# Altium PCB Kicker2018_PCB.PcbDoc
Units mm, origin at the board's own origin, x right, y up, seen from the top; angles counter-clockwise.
Board outline 66.22 x 43.08 mm, 2 copper layers (Top Layer, Bottom Layer); 38 components, 26 nets, 134 pads, 5 vias.
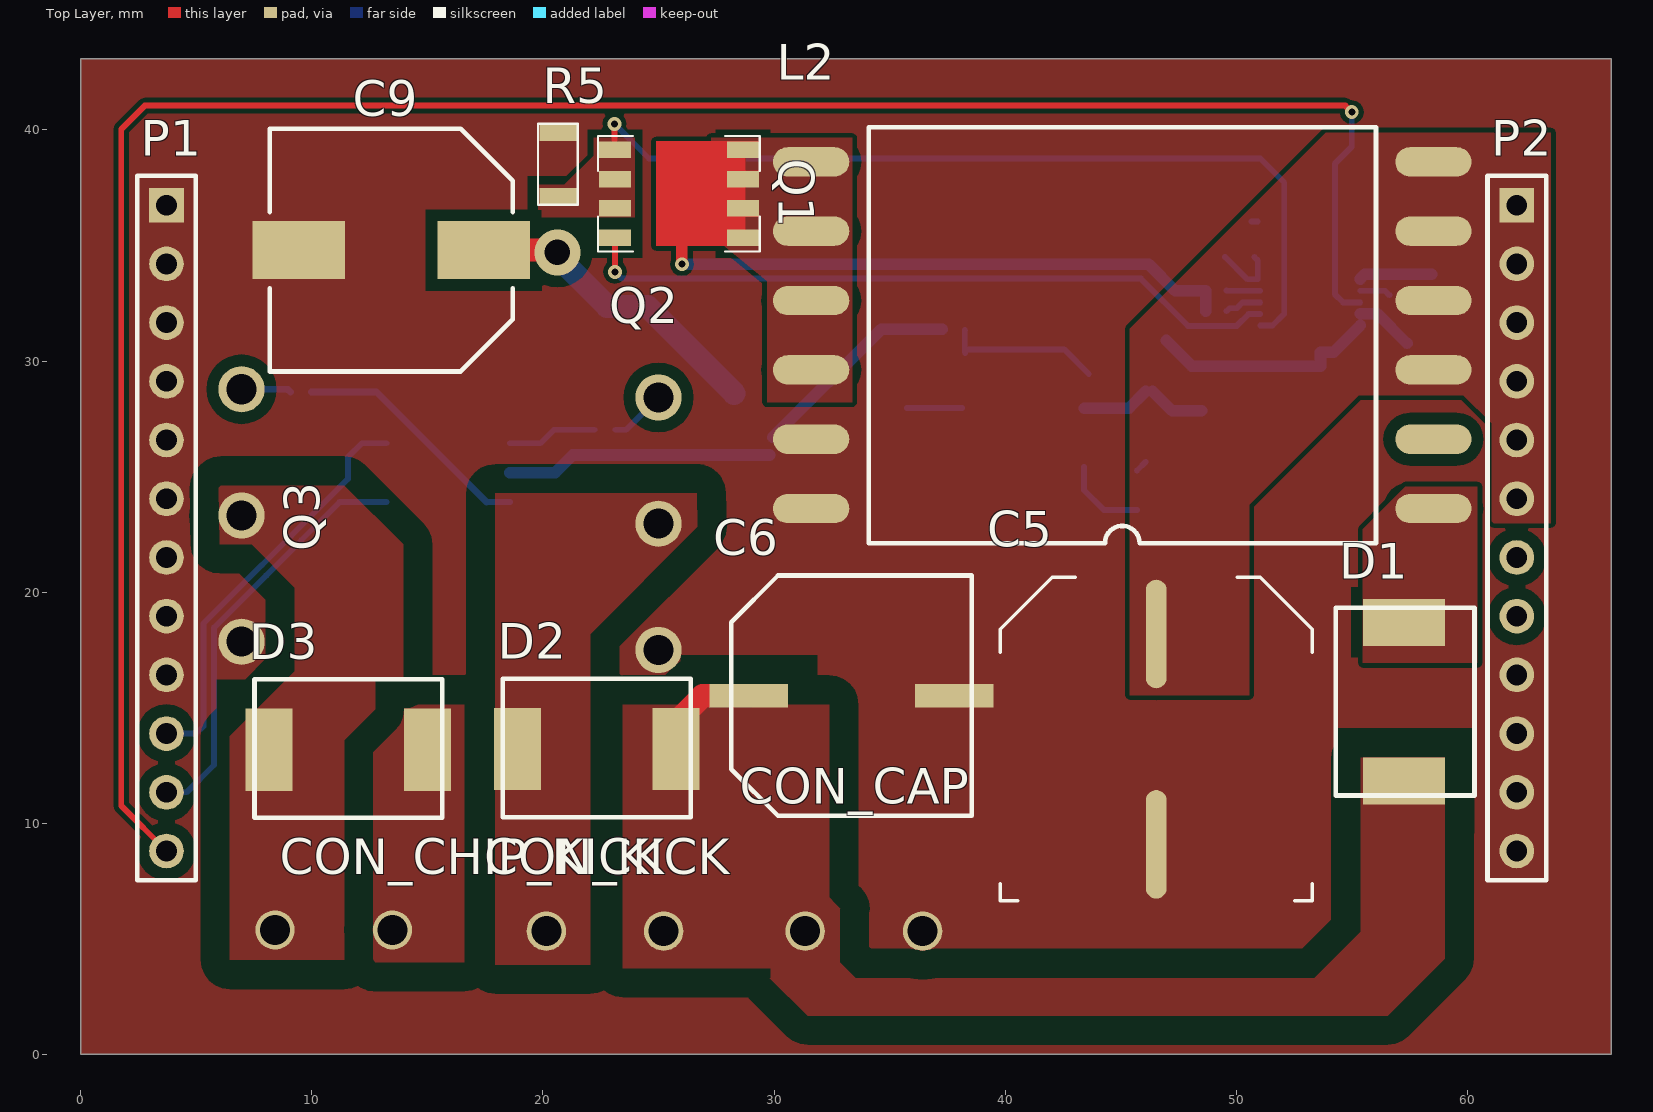
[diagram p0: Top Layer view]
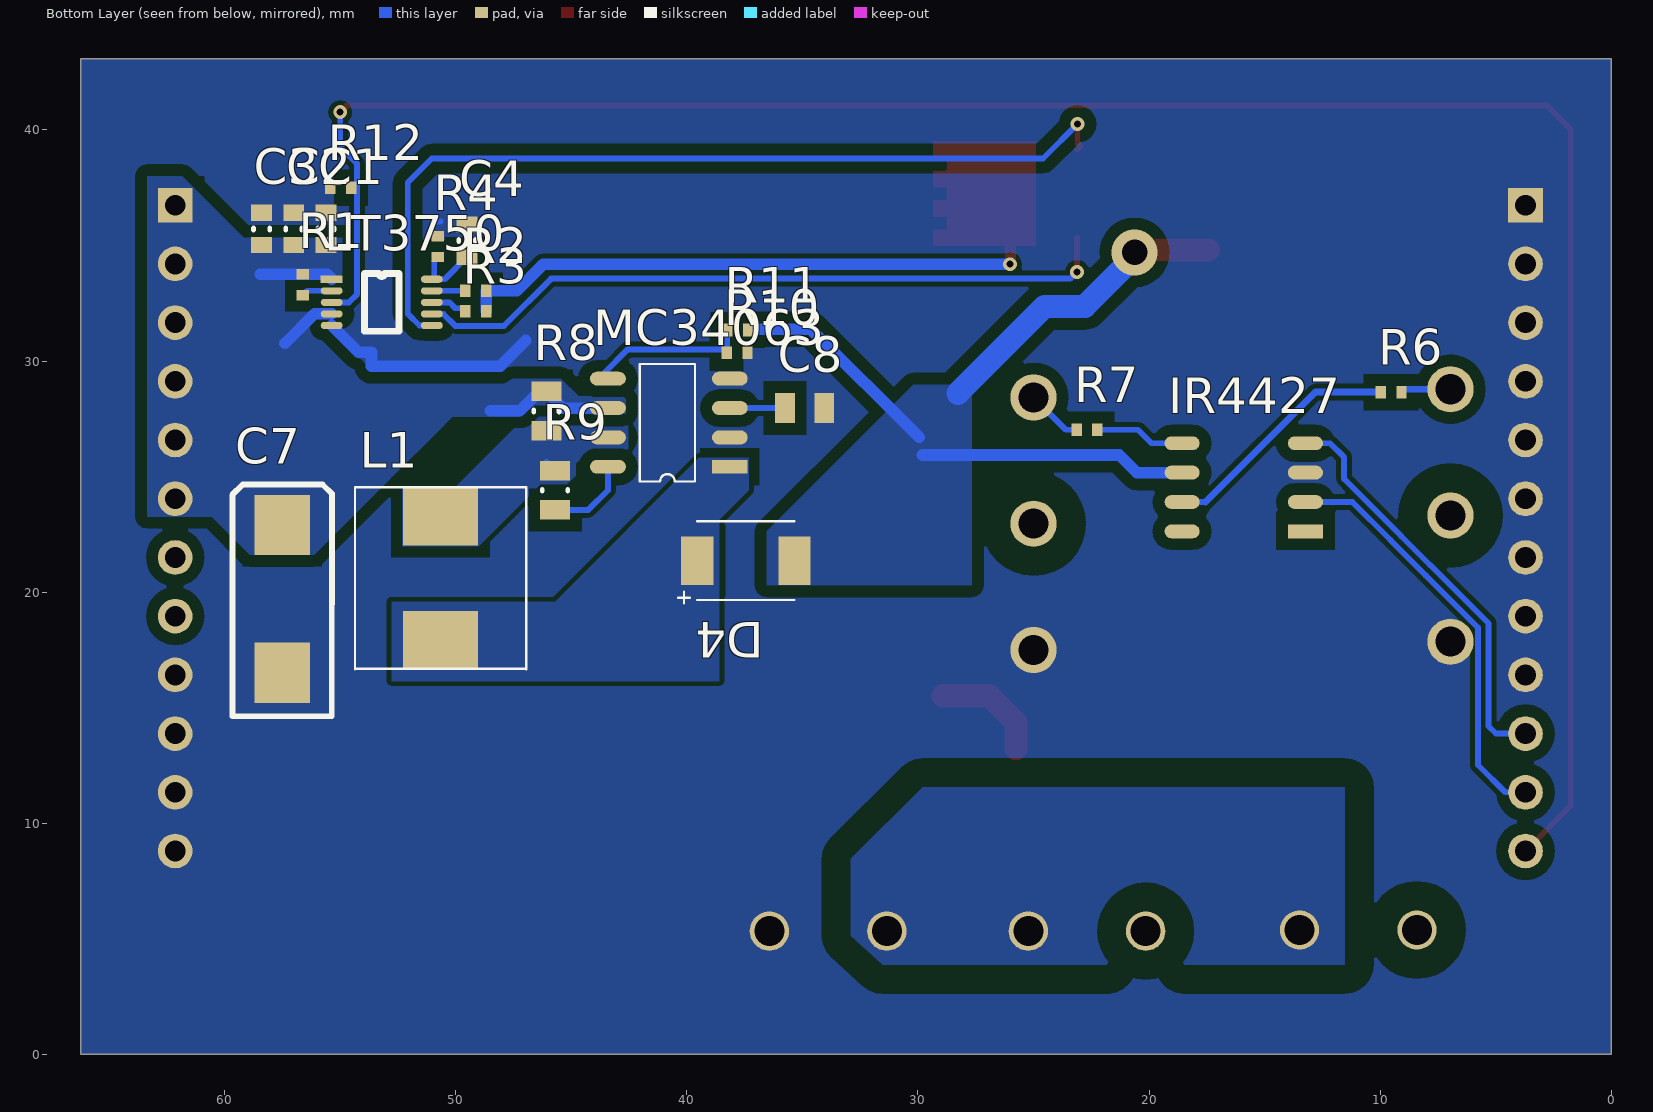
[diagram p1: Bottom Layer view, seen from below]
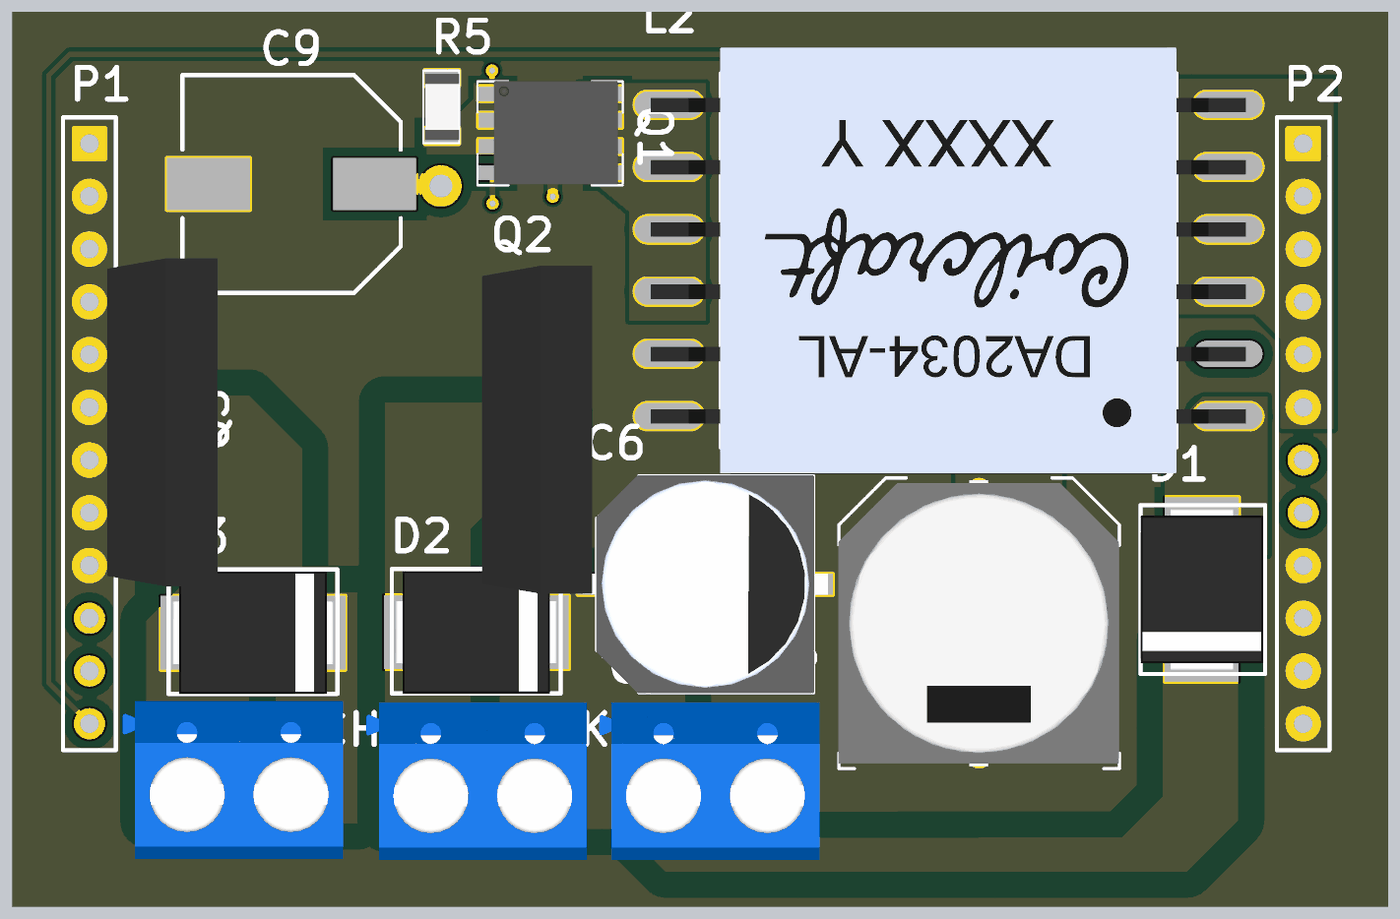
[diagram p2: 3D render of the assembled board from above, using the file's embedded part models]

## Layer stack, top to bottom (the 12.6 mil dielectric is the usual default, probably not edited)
Top Solder: solder mask 0.0102, Solder Resist, Dk 3.5
Top Layer: signal copper 0.0356
Dielectric 1: dielectric 0.32, FR-4, Dk 4.8
Bottom Layer: signal copper 0.0356
Bottom Solder: solder mask 0.0102, Solder Resist, Dk 3.5

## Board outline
0,43.078 0,0 66.218,0 66.218,43.078

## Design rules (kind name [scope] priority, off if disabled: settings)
Clearance "Vs Clearence" [InNet('Vs')] p1: gap=0.5 ignorepadtopadclearanceinfootprint=TRUE
Clearance NetLT3750_6 [OnLayer('Bottom Layer') vs InNet('NetLT3750_6')] p2: gap=0.5 ignorepadtopadclearanceinfootprint=TRUE
Clearance "VCC Clearence" [InNet('VCC') vs OnLayer('Bottom Layer')] p3: gap=0.5 ignorepadtopadclearanceinfootprint=TRUE
Clearance HV [InNetClass('HV')] p4: gap=1.25 ignorepadtopadclearanceinfootprint=TRUE
Clearance [All] p5: gap=0.2 ignorepadtopadclearanceinfootprint=TRUE except(0.5: SMDPad-Poly THPad-Poly)
Height [All] p1: minheight=0 maxheight=50 prefheight=12.7
PlaneConnect [All] p1: planeconnectstyle=Direct reliefexpansion=0.508 reliefentries=4 reliefconductorwidth=0.254 reliefairgap=0.254
PolygonConnect [All] p1: connectstyle=Direct reliefconductorwidth=0.254 reliefentries=4 polygonreliefangle="90 Angle" airgapwidth=0.254
RoutingVias [All] p1: holewidth=0.711 width=1.27 viastyle="Through Hole" minholewidth=0.711 minwidth=1.27 maxholewidth=0.711 maxwidth=1.27
SolderMaskExpansion [All] p1: expansion=0.102
Width [All] p1: maxlimit=5 minlimit=0.254 preferedwidth=0.254
28 further rules are at their usual default settings.

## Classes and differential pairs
net class HV: Cap+ CHIP_KICK- KICK-

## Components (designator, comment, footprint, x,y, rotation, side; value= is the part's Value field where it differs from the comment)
C1 "10uF" CAPC0603(1608)55_L 55.601,35.712 r90 bottom
C2 "10uF" CAPC0603(1608)55_L 56.998,35.712 r90 bottom
C3 "10uF" CAPC0603(1608)55_L 58.395,35.712 r90 bottom
C4 "100pF" CAPC0603(1608)55_L 49.505,35.204 r270 bottom
C5 "100uF" PCBComponent#1 46.533,13.64 r180 top
C6 "22uF" "CAP ALUM 22UF 250V" 33.35,15.519 r180 top
C7 "100uF" 7343-CAPPOL 57.506,19.71 r270 bottom
C8 "180pF" 0805-CAP 34.9,27.965 r0 bottom
C9 "220uF" NIC-CAPA2-10X10_V 13.437,34.798 r180 top
CON_CAP "OSTTA024163" "Term Block 2P" 33.884,5.334 r0 top
CON_CHIP_KICK "OSTTA024163" "Term Block 2P" 10.947,5.385 r0 top
CON_KICK "OSTTA024163" "Term Block 2P" 22.682,5.334 r0 top
D1 "ES3J" Diode 57.252,15.265 r90 top
D2 "ES3J" Diode 22.327,13.208 r180 top
D3 "ES3J" Diode 11.582,13.183 r180 top
D4 "PMEG3050EP,115" PCBComponent#2 37.44,21.361 r0 bottom
IR4427 "GATE DRIVER" IR4427 15.9,24.536 r0 bottom
L1 "100uH" Inductor 50.648,20.599 r90 bottom
L2 "DA2034 Transformer" "DA2034 Transformer" 58.522,23.616 r180 top
LT3750 "Flyback Regulator" LT3750 55.359,33.537 r180 bottom
MC34063 "Switching Voltage Regulator" MC34063 38.136,25.425 r0 bottom
P1 "Header 12" HDR1X12 3.711,36.74 r270 top
P2 "Header 12" HDR1X12 62.131,36.74 r270 top
Q1 "CSD18540Q5BT" PCBComponent#3 25.883,37.236 r180 top
Q2 "IRG4PC50FD" IRG4PC50FD 24.994,22.962 r270 top
Q3 "IRG4PC50FD" IRG4PC50FD 6.96,23.317 r270 top
R1 "100K" 0402-RES-HD 56.617,33.299 r270 bottom value=100k
R2 "33K" 0402-RES-HD 49.124,33.045 r180 bottom
R3 "42K2" 0402-RES-HD 49.124,32.156 r180 bottom value=42.2K
R4 "2K2" 0402-RES-HD 50.775,34.95 r90 bottom value=2.2K
R5 "15m" RES1206 20.676,38.506 r90 top
R6 "10R" 0402-RES-HD 9.525,28.651 r180 bottom value=10
R7 "10R" 0402-RES-HD 22.682,27.026 r0 bottom value=10
R8 "1R" 0805-RES 46.076,27.838 r270 bottom
R9 "160R" 0805-RES 45.695,24.409 r90 bottom value=160
R10 "1K" 0402-RES-HD 37.821,30.353 r0 bottom
R11 "11K1" 0402-RES-HD 37.795,31.344 r0 bottom value=11k1
R12 "1K" 0402-RES-HD 54.966,37.49 r180 bottom

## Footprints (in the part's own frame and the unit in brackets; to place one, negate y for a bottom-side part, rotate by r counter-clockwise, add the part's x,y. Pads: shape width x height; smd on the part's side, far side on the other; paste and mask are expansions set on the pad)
0402-RES-HD [mm] "Chip Resistor, Body 1.0x0.5mm, IPC High Density"
  rect 0.45x0.55 smd: 1(-0.45,0) 2(0.45,0)
  body extent -0.52,-0.27 0.53,0.28, height 0.4
0805-CAP [mm] "Chip Resistor, Body 2.0x1.3mm, IPC High Density"
  rect 0.85x1.3 smd: 1(-0.85,0) 2(0.85,0)
  body extent -1.1,-0.67 1.1,0.68, height 0.7
0805-RES [mm] "Chip Resistor, Body 2.0x1.3mm, IPC High Density"
  rect 0.85x1.3 smd: 1(-0.85,0) 2(0.85,0)
  silkscreen extent -0.05,-0.55 0.05,0.55, body extent -1.1,-0.67 1.1,0.68, height 0.7
7343-CAPPOL [mm] "SMT Capacitor, 2 Leads, Body 7.3x4.3mm"
  rect 2.6x2.4 smd: 1(-3.202,0.007) 2(3.198,0.007)
  silkscreen extent -4.95,-2.15 5.08,2.16, body extent -3.49,-2.03 3.51,2.04, height 4.05
"CAP ALUM 22UF 250V" [mm] "22uF"
  rect 3.4x1 smd: Cap+(4.445,0) Cap-(-4.445,0)
  silkscreen extent -5.2,-5.2 5.2,5.2, body extent -5.9,-5.25 5.9,5.25, height 10.3
CAPC0603(1608)55_L [mm] "Chip Capacitor, Body 1.6x0.8mm, Height 0.55mm, IPC High Density"
  rect 0.7x0.9 smd: 1(-0.7,0) 2(0.7,0)
  silkscreen extent -0.05,-0.35 0.05,0.35, body extent -0.87,-0.47 0.88,0.48, height 0.55
"DA2034 Transformer" [mm]
  oval 3.3x1.27 smd: 1(0,0) 2(0,-3) 3(0,-6) 4(0,-9) 5(0,-12) 6(0,-15) 7(26.92,-15) 8(26.92,-12) 9(26.92,-9) 10(26.92,-6) 11(26.92,-3) 12(26.92,0)
  silkscreen extent 2.48,-16.5 24.44,1.5, body extent -0.86,-17.78 27.79,2.79, height 11.18
Diode [mil]
  rect 80x140 smd: D1+(-135,0) D1-(135,0)
  silkscreen extent -160,-120 160,116, body extent -154,-116 154,116, height 95
HDR1X12 [mm] "Connector; Header; 12 Position"
  rect 1.5x1.5 hole 0.9: 1(0,0)
  round 1.5 hole 0.9: 2(2.54,0) 3(5.08,0) 4(7.62,0) 5(10.16,0) 6(12.7,0) 7(15.24,0) 8(17.78,0) 9(20.32,0) 10(22.86,0) 11(25.4,0) 12(27.94,0)
  silkscreen extent -1.27,-1.27 29.21,1.27
Inductor [mm]
  rect 2.5x3.25 smd: 1(-2.667,0) 2(2.667,0)
  silkscreen extent -3.94,-3.7 3.94,3.7, body extent -3.65,-3.65 3.65,3.65, height 4.2
IR4427 [mm]
  rect 1.52x0.6 smd: 1(-2.667,1.905)
  oval 1.52x0.6 smd: 2(-2.667,0.635) 3(-2.667,-0.635) 4(-2.667,-1.905) 5(2.667,-1.905) 6(2.667,-0.635) 7(2.667,0.635) 8(2.667,1.905)
  body extent -3,-2.45 3,2.45, height 1.75
IRG4PC50FD [mm] "IGBT Transistors 600V FAST 1-8 KHZ COPACK IGBT"
  round 2 hole 1.3: 1(0,0) 2(-5.461,0) 3(5.461,0)
  body extent -7.9,-2.39 7.9,2.92, height 34.13
LT3750 [mm]
  rect 0.95x0.305 smd: 1(0,0)
  oval 0.95x0.305 smd: 2(0,-0.5) 3(0,-1) 4(0,-1.5) 5(0,-2) 6(4.33,-2) 7(4.33,-1.5) 8(4.33,-1) 9(4.33,-0.5) 10(4.33,0)
  silkscreen extent 1.41,-2.25 2.92,0.25, body extent -0.29,-2.52 4.61,0.48, height 1.15
MC34063 [mm]
  rect 1.55x0.6 smd: 1(0,0)
  oval 1.55x0.6 smd: 2(0,-1.27) 3(0,-2.54) 4(0,-3.81) 5(5.273,-3.81) 6(5.273,-2.54) 7(5.273,-1.27) 8(5.273,0)
  silkscreen extent 1.51,-4.44 3.89,0.64, body extent -0.38,-4.32 5.6,0.58, height 1.58
NIC-CAPA2-10X10_V [mm] "Aluminum Electrolytic Capacitor, Diameter 10mm, Height 10.8mm, Pitch 8mm"
  rect 4x2.5 smd: 1(-4,0) 2(4,0)
  silkscreen extent -5.25,-5.25 5.25,5.25, body extent -5,-5 5,5, height 10.8
PCBComponent#1 [mm]
  oval 0.9x4.7 smd: 1(0,4.55) 2(0,-4.55)
  silkscreen extent -6.75,-7 6.75,7, body extent -6.73,-6.9 6.77,6.9, height 13.5
PCBComponent#2 [mm]
  rect 1.4x2.1 smd: 1(-2.1,0) 2(2.1,0)
  silkscreen extent -2.1,-1.7 2.93,1.85, body extent -2.5,-1.35 2.5,1.35, height 1.1
PCBComponent#3 [mm]
  rect 1.372x0.711 smd: 1(2.769,-1.905) 2(2.769,-0.635) 3(2.769,0.635) 4(2.769,1.905) 5(-2.769,1.905) 6(-2.769,0.635) 7(-2.769,-0.635) 8(-2.769,-1.905)
  Top Layer region: -3.454,2.261 0.991,2.261 0.991,-2.261 -3.454,-2.261 -3.454,-1.549 -2.87,-1.549 -2.87,-0.991 -3.454,-0.991 -3.454,-0.279 -2.87,-0.279 -2.87,0.279 -3.454,0.279 -3.454,0.991 -2.87,0.991 -2.87,1.549 -3.454,1.549
  silkscreen extent -3.5,-2.5 3.5,2.5, body extent -3.28,-2.53 2.72,2.47, height 1.1
RES1206 [mil]
  rect 30x65 smd: 1(-55,0) 2(55,0)
  silkscreen extent -69,-33 69,35, body extent -63,-33 63,33, height 21
"Term Block 2P" [mm]
  round 1.7 hole 1.3: 1(-2.54,0) 2(2.54,0)
  body extent -5.64,-3.1 4.96,4.5, height 10

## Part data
C1 C2 C3: library part C0603-10uF-16V-1, "CAP CER 10UF 16V X5R 0603", Part No=EMK107BBJ106MA-T
C4: library part CC0603--1, "CAP CER 100PF 50V NP0 0603", Part No=GRM1885C1H101JA01D
C5: library part CA-100uF-3, "CAP ALUM 100UF 20% 80V SMD"
C6: library part "CAP ALUM 22UF 250V"
C7: library part CT2917-100uF-1, "CAP TANT 100uF 25V 20% ESR = 30mOhm @ 100 kHz", Part No=T521X107M025ATE030
C8: library part CC0805-180pF-2, "CAP CER 180PF 50V NP0 0805", Part No=C0805C181K5GACTU
C9: library part CA-220uF-1, "CAP ALUM 220uF 20% 50V  ESR = 0,18 ohms  Radial DIA 10mm HEIGH 10,2mm", Part No=EEEFK1H221P
CON_CAP CON_CHIP_KICK CON_KICK: library part "Term Block 2P", "2 Position Wire to Board Terminal Block Horizontal with Board 0.200\" (5.08mm) Through Hole"
D4: library part PMEG3050EP,115-01.A.5, "DIODE SCHOTTKY 30V 5A SOD128"
IR4427: library part IR4427, "IC DRIVER DUAL LOW SIDE 8-SOIC"
L1: library part Inductor, "Fixed Inductors 100uH 0.86A SMT"
LT3750: library part LT3750
MC34063: library part MC34063
P1 P2: "Header, 12-Pin"
Q1: library part CSD18540Q5BT-1, "MOSFET N-CH 60V 100A 8VSON"
Q2 Q3: "IGBT Transistors 600V FAST 1-8 KHZ COPACK IGBT"
R1: library part R0402-100K-11, "RES 100K OHM 1/10W 1% 0402 SMD 1", Part No=ERJ-2GEJ104X
R2: library part R0402-33K-7, "RES 33K OHM 1/10W 1% 0402 SMD", Part No=ERJ-2RKF3302X
R3: library part RESISTOR, "RES 42.2K OHM 1/10W 1% 0402 SMD", Part No=ERJ-2RKF4222X
R4: library part R0402-2K2-5, "RES 2.2K OHM 1/10W 1% 0402 SMD", Part No=ERJ-2RKF2201X
R5: library part Res2, "Resistor"
R6 R7: library part R0402-10R-6, "RES 10 OHM 1/10W 1% 0402 SMD", Part No=ERJ-2RKF10R0X
R8: library part R0805-1R-1%-1, "RES SMD 1 OHM 1% 1/8W 0805", Part No=CRCW08051R00FKEA
R9: library part R0805-160R-5, "RES 160 OHM 1/8W .5% 0805 SMD", Part No=ERA-6AED161V
R10 R12: library part R0402-1K-A.9, "RES 1K OHM 1/10W 1% 0402 SMD", Part No=ERJ-2RKF1001X
R11: library part R0402-11K1-1, "RES 11.1 KOHM 1/16W 0.1% 0402 SMD", Part No=TNPW040211K1BEED

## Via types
v1: diameter 0.6, hole 0.3, Top Layer to Bottom Layer, 4 vias
v2: diameter 2, hole 1.1, Top Layer to Bottom Layer, 1 vias

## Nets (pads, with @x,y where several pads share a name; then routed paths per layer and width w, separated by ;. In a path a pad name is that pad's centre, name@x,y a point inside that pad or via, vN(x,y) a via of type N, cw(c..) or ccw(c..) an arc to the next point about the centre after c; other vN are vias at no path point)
Cap+: C6.Cap+ CON_CAP.1 CON_CHIP_KICK.2 CON_KICK.2 D1.D1+ D2.D1+ D3.D1+ | length 4.8
  Top Layer w1: D2.D1+ 25.756,14.374 26.901,15.519 C6.Cap+
Cap-: C1.2 C2.2 C3.2 C4.1 C5.1 C6.Cap- C7.2 C8.1 C9.2 CON_CAP.2 IR4427.3 L2.11 L2.12 LT3750.5 MC34063.2 MC34063.4 P1.1 P1.2 P1.3 P1.4 P1.5 P1.6 P1.7 P1.8 P1.9 P2.9 P2.10 P2.11 P2.12 Q2.3 Q3.3 R4.2 R5.2 R10.1 R12.1 | length 10.2
  Bottom Layer w0.254: 50.648,36.031 50.922,36.031
  Bottom Layer w0.5: 46.965,30.886 48.075,29.776 53.638,29.776 53.638,30.378 54.2,30.378 LT3750.5
CHARGE_ENABLE: LT3750.3 P1.12 R12.2 | length 95.2
  Top Layer w0.254: P1.12 1.753,10.758 1.753,40.03 2.769,41.046 54.712,41.046 v1(54.991,40.767)
  Bottom Layer w0.254: v1(54.991,40.767) 54.991,39.268 54.257,38.534 54.257,32.891 54.61,32.537 LT3750.3
CHIP_KICK: Q3.2 R6.2 | length 2.2
  Bottom Layer w0.3: Q3.2 8.948,28.778 R6.2
CHIP_KICK-: CON_CHIP_KICK.1 D3.D1- Q3.1
CHIP_KICK_SIGNAL: IR4427.4 P1.10 | length 17.9
  Bottom Layer w0.254: P1.10 4.99,13.88 5.309,14.199 5.309,18.651 7.836,21.178 7.846,21.178 9.099,22.431 9.099,22.441 11.557,24.899 11.557,25.832 12.167,26.441 IR4427.4
KICK: Q2.2 R7.2 | length 2.4
  Bottom Layer w0.254: R7.2 23.597,27.026 Q2.2
KICK-: CON_KICK.1 D2.D1- Q2.1
KICK_SIGNAL: IR4427.2 P1.11 | length 18.2
  Bottom Layer w0.254: P1.11 4.584,11.34 5.763,12.519 5.763,18.463 8.024,20.724 8.034,20.724 9.553,22.243 9.553,22.253 11.201,23.901 IR4427.2
NetC4_2: C4.2 LT3750.10 R4.1 | length 2.8
  Bottom Layer w0.254: C4.2 50.472,33.537 50.922,33.537 50.922,34.353 R4.1
NetC8_2: C8.2 MC34063.3 | length 2.4
  Bottom Layer w0.254: C8.2 MC34063.3
NetD1_D1-: D1.D1- L2.1
NetD4_2: D4.2 L1.1 MC34063.1
NetIR4427_5: IR4427.5 R7.1 | length 3.9
  Bottom Layer w0.254: IR4427.5 19.888,26.441 20.472,27.026 R7.1
NetIR4427_7: IR4427.7 R6.1 | length 10.6
  Bottom Layer w0.254: 17.551,23.901 IR4427.7
  Bottom Layer w0.3: R6.1 12.802,28.651 17.551,23.901
NetL1_2: L1.2 MC34063.7 R8.2 R9.2 | length 0.5
  Bottom Layer w0.254: R9.2 R9.2@46.076,25.64
NetL2_7: L2.7 L2.8 L2.9 L2.10 Q1.5 Q1.6 Q1.7 Q1.8 R2.2 R3.2 | length 28.8
  Top Layer w0.5: v1(26.01,34.188) 26.01,36.068 26.543,36.601 Q1.6
  Bottom Layer w0.5: v1(26.01,34.188) 46.203,34.188 47.346,33.045 R2.2 R3.2
NetLT3750_2: LT3750.2 R1.2 | length 1.3
  Bottom Layer w0.254: LT3750.2 56.429,33.037 R1.2
NetLT3750_6: LT3750.6 Q1.1 Q1.2 Q1.3 R5.1 | length 38.2
  Top Layer w0.254: v1(23.089,40.259) 23.089,39.421 22.962,39.294 Q1.1
  Bottom Layer w0.254: v1(23.089,40.259) 24.587,38.76 51.029,38.76 52.07,37.719 52.07,32.045 51.562,31.537 LT3750.6
NetLT3750_7: LT3750.7 Q1.4 | length 30.6
  Top Layer w0.254: v1(23.114,33.858) Q1.4
  Bottom Layer w0.254: v1(23.114,33.858) 23.411,33.561 45.864,33.561 47.904,31.521 50.013,31.521 50.529,32.037 LT3750.7
NetLT3750_8: LT3750.8 R3.1 | length 1.6
  Bottom Layer w0.254: R3.1 49.701,32.283 50.013,32.283 50.267,32.537 LT3750.8
NetLT3750_9: LT3750.9 R2.1 | length 1.5
  Bottom Layer w0.254: R2.1 49.582,33.037 LT3750.9
NetMC34063_5: MC34063.5 R10.2 R11.2 | length 7
  Bottom Layer w0.254: R11.2@38.271,31.318 R11.2 38.245,30.378 R10.2 38.271,30.505 42.546,30.505 MC34063.5@43.612,29.439
NetMC34063_8: MC34063.8 R9.1 | length 3.7
  Bottom Layer w0.254: MC34063.8 43.409,24.409 44.259,23.559 R9.1
VCC: C1.1 C2.1 C3.1 C5.2 C7.1 L2.3 L2.4 L2.5 L2.6 LT3750.1 LT3750.4 MC34063.6 P2.1 P2.2 P2.3 P2.4 P2.5 P2.6 R1.1 R8.1 | length 11.5
  Bottom Layer w0.254: R8.1 R8.1@46.369,28.688
  Bottom Layer w0.5: MC34063.6 45.353,27.965 R8.1 ; R8.1@46.369,28.688 47.219,27.838 48.489,27.838 ; LT3750.4 56.101,32.037 57.379,30.759 ; LT3750.1 55.359,33.565 55.543,33.749 R1.1 58.453,33.749
Vs: C9.1 D4.1 IR4427.6 R11.1 | length 34.6
  Top Layer w1: C9.1 20.523,34.798 v2(20.625,34.696)
  Bottom Layer w0.5: IR4427.6 20.523,25.171 21.285,25.933 29.82,25.933 ; 29.947,26.695 34.629,31.378 R11.1@37.27,31.378
  Bottom Layer w1: v2(20.625,34.696) 20.437,34.696 22.774,32.36 24.511,32.36 28.27,28.6
pads on no net: IR4427.1 IR4427.8 L2.2 P2.7 P2.8

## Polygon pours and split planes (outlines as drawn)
Cap+ on Top Layer "Top Layer-Cap+" (solid, pour order 37): 55.372,12.827 59.004,12.827 59.004,4.14 56.54,1.676 31.445,1.676 29.82,3.302 29.845,3.327 29.845,6.985 32.182,6.985 32.868,6.299 32.842,6.274 32.842,3.988 33.528,3.302 53.391,3.327 55.372,5.309
Cap+ on Top Layer "CAP+_L01_P041" (solid, remove dead copper, pour order 41): 16.604,15.138 16.604,3.991 12.065,3.983 12.065,15.138
Cap+ on Top Layer "CAP+_L01_P039" (solid, remove dead copper, pour order 39): 32.385,15.138 32.385,3.738 23.444,3.738 23.444,15.138
Cap- on Top Layer "GND" (solid, remove dead copper, pour order 43): 0,0 0,43.078 66.218,43.078 66.218,0
KICK- on Top Layer "KICK-_L01_P035" (solid, remove dead copper, pour order 35): 26.652,24.282 17.932,24.282 17.932,3.886 22.047,3.886 22.047,18.186 26.682,22.821
CHIP_KICK- on Top Layer "CHIP_KICK-_L01_P034" (solid, remove dead copper, pour order 34): 6.02,22.073 7.391,22.073 9.271,20.193 9.271,16.586 6.452,13.767 6.452,4.089 11.405,4.089 11.405,13.589 13.945,16.129 13.945,22.073 11.405,24.613 5.976,24.613
VCC on Top Layer "VCC Top" (solid, remove dead copper, pour order 26): 63.602,22.987 61.036,22.987 61.036,27.305 59.817,28.524 55.296,28.524 50.546,23.774 50.546,15.545 45.39,15.545 45.39,31.394 53.873,39.878 63.602,39.878
NetD1_D1- on Top Layer "HV D1-" (solid, remove dead copper, pour order 28): 60.427,24.562 60.427,16.942 55.474,16.942 55.474,22.728 57.307,24.562
NetL2_7 on Top Layer "HV L2_7" (solid, remove dead copper, pour order 29): 33.376,39.649 33.376,28.219 29.693,28.219 29.693,33.456 27.28,35.443 27.28,39.649
NetLT3750_6 on Top Layer "NETLT3750_6_L01_P025" (solid, remove dead copper, pour order 25): 23.978,36.22 19.787,36.22 19.787,37.617 20.93,37.617 22.2,38.887 22.2,39.649 23.978,39.649
Cap- on Bottom Layer "GND" (solid, remove dead copper, pour order 45): 0,43.078 0,0 66.218,0 66.218,43.078
VCC on Bottom Layer "VCC Bottom" (solid, remove dead copper, pour order 22): 63.348,23.266 60.554,23.266 58.903,21.615 56.109,21.615 50.775,26.949 50.14,27.584 42.647,27.584 42.647,28.473 44.679,28.473 45.441,29.235 53.569,29.235 54.585,30.251 54.585,32.918 54.585,35.331 59.157,35.331 61.824,37.998 63.348,37.998
NetL1_2 on Bottom Layer "NETL1_2_L02_P021" (solid, remove dead copper, pour order 21): 45.06,27.584 46.965,27.584 50.013,24.536 52.299,24.536 52.299,21.996 48.997,21.996 46.33,24.663 45.187,24.663 44.806,25.044 44.806,25.552 44.171,26.187 42.52,26.187 42.52,27.203 44.679,27.203
Cap+ on Bottom Layer "HV Cap+" (solid, remove dead copper, pour order 23): 32.893,5.131 32.893,8.458 29.794,11.557 11.54,11.557 11.54,3.887 16.696,3.886 22.665,3.887 31.53,3.886
NetD4_2 on Bottom Layer "NETD4_2_L02_P019" (solid, remove dead copper, pour order 19): 52.765,16.154 38.583,16.154 38.583,23.139 37.313,24.409 37.313,25.806 39.472,25.806 45.695,19.583 52.765,19.583
Vs on Bottom Layer "VS_L02_P020" (solid, remove dead copper, pour order 20): 36.54,22.642 30.201,28.981 27.661,28.981 27.661,20.295 36.54,20.295

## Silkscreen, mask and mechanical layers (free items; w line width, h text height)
Mechanical 1:
  lines w0.3: 0,0 66.218,0 ; 0,0 0,43.078 ; 0,0 66.218,0 ; 0,0 0,43.078 ; 0,43.078 66.218,43.078 ; 0,43.078 66.218,43.078 ; 66.218,0 66.218,43.078 ; 66.218,0 66.218,43.078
